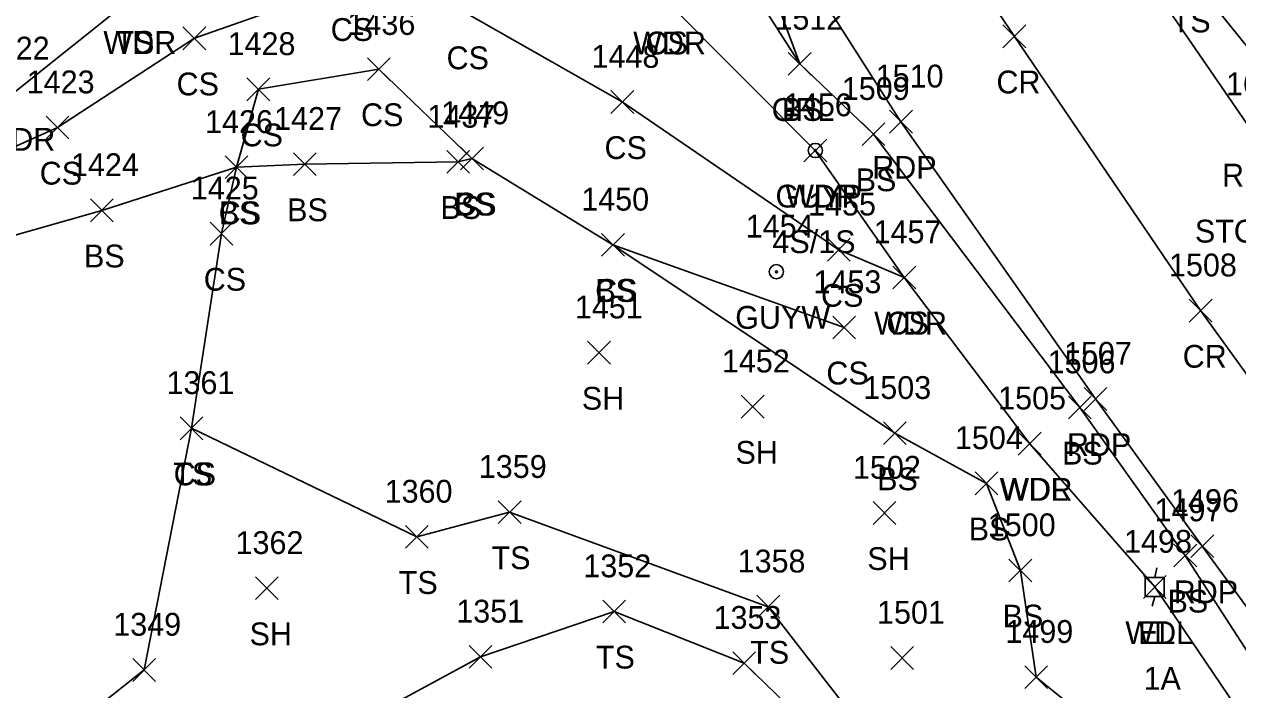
# Model space of a CAD drawing. Extents: x 1499292 to 1501024, y 534584 to 538043.
# Drawn here: x 1499781.4 to 1499887.8, y 537564.4 to 537622.8 of the extents above; entities that cross this region are included whole.
import ezdxf

# ---------------------------------------------------------------- set-up
doc = ezdxf.new("R2010")
doc.units = 0
for name, color, linetype in [('L_A', 7, 'Continuous'), ('L_I', 7, 'Continuous'), ('L_TIC', 7, 'Continuous'), ('LAWA', 7, 'Continuous'), ('LELB', 7, 'Continuous'), ('P_A', 7, 'Continuous'), ('P_I', 7, 'Continuous'), ('P_TIC', 7, 'Continuous'), ('PET', 7, 'Continuous'), ('PRC', 7, 'Continuous'), ('R_A', 7, 'Continuous'), ('R_I', 7, 'Continuous'), ('R_TIC', 7, 'Continuous'), ('RGR', 7, 'Continuous'), ('S_C', 7, 'Continuous'), ('U_A', 7, 'Continuous'), ('U_C', 7, 'Continuous'), ('U_I', 7, 'Continuous'), ('UEPT', 7, 'Continuous'), ('UPGW', 7, 'Continuous')]:
    doc.layers.add(name, color=color, linetype=linetype)

msp = doc.modelspace()

# ---------------------------------------------------------------- linework, layer by layer
at = {"layer": 'L_TIC'}
for points in [[(1499795.35, 537620.54), (1499797.35, 537622.54)], [(1499797.35, 537620.54), (1499795.35, 537622.54)], [(1499811.52, 537617.84), (1499813.52, 537619.84)], [(1499813.52, 537617.84), (1499811.52, 537619.84)], [(1499848.42, 537618.3), (1499850.42, 537620.3)], [(1499850.42, 537618.3), (1499848.42, 537620.3)], [(1499800.96, 537616.07), (1499802.96, 537618.07)], [(1499802.96, 537616.07), (1499800.96, 537618.07)], [(1499832.87, 537614.96), (1499834.87, 537616.96)], [(1499834.87, 537614.96), (1499832.87, 537616.96)], [(1499783.35, 537612.72), (1499785.35, 537614.72)], [(1499785.35, 537612.72), (1499783.35, 537614.72)], [(1499854.89, 537612.14), (1499856.89, 537614.14)], [(1499856.89, 537612.14), (1499854.89, 537614.14)], [(1499849.79, 537610.71), (1499851.79, 537612.71)], [(1499851.79, 537610.71), (1499849.79, 537612.71)], [(1499799.04, 537609.24), (1499801.04, 537611.24)], [(1499801.04, 537609.24), (1499799.04, 537611.24)], [(1499799.04, 537609.24), (1499801.04, 537611.24)], [(1499801.04, 537609.24), (1499799.04, 537611.24)], [(1499805.04, 537609.51), (1499807.04, 537611.51)], [(1499807.04, 537609.51), (1499805.04, 537611.51)], [(1499818.47, 537609.71), (1499820.47, 537611.71)], [(1499820.47, 537609.71), (1499818.47, 537611.71)], [(1499819.69, 537610.01), (1499821.69, 537612.01)], [(1499821.69, 537610.01), (1499819.69, 537612.01)], [(1499819.69, 537610.01), (1499821.69, 537612.01)], [(1499821.69, 537610.01), (1499819.69, 537612.01)], [(1499787.23, 537605.46), (1499789.23, 537607.46)], [(1499789.23, 537605.46), (1499787.23, 537607.46)], [(1499797.73, 537603.42), (1499799.73, 537605.42)], [(1499799.73, 537603.42), (1499797.73, 537605.42)], [(1499832.05, 537602.44), (1499834.05, 537604.44)], [(1499834.05, 537602.44), (1499832.05, 537604.44)], [(1499832.05, 537602.44), (1499834.05, 537604.44)], [(1499834.05, 537602.44), (1499832.05, 537604.44)], [(1499851.85, 537602.01), (1499853.85, 537604.01)], [(1499853.85, 537602.01), (1499851.85, 537604.01)], [(1499857.59, 537599.58), (1499859.59, 537601.58)], [(1499859.59, 537599.58), (1499857.59, 537601.58)], [(1499857.59, 537599.58), (1499859.59, 537601.58)], [(1499859.59, 537599.58), (1499857.59, 537601.58)], [(1499852.32, 537595.2), (1499854.32, 537597.2)], [(1499854.32, 537595.2), (1499852.32, 537597.2)], [(1499830.83, 537592.99), (1499832.83, 537594.99)], [(1499832.83, 537592.99), (1499830.83, 537594.99)], [(1499844.3, 537588.25), (1499846.3, 537590.25)], [(1499846.3, 537588.25), (1499844.3, 537590.25)], [(1499872.98, 537588.18), (1499874.98, 537590.18)], [(1499874.98, 537588.18), (1499872.98, 537590.18)], [(1499795.09, 537586.36), (1499797.09, 537588.36)], [(1499797.09, 537586.36), (1499795.09, 537588.36)], [(1499795.09, 537586.36), (1499797.09, 537588.36)], [(1499797.09, 537586.36), (1499795.09, 537588.36)], [(1499856.77, 537585.93), (1499858.77, 537587.93)], [(1499858.77, 537585.93), (1499856.77, 537587.93)], [(1499868.59, 537585.01), (1499870.59, 537587.01)], [(1499870.59, 537585.01), (1499868.59, 537587.01)], [(1499868.59, 537585.01), (1499870.59, 537587.01)], [(1499870.59, 537585.01), (1499868.59, 537587.01)], [(1499864.8, 537581.53), (1499866.8, 537583.53)], [(1499866.8, 537581.53), (1499864.8, 537583.53)], [(1499864.8, 537581.53), (1499866.8, 537583.53)], [(1499866.8, 537581.53), (1499864.8, 537583.53)], [(1499822.99, 537579.01), (1499824.99, 537581.01)], [(1499824.99, 537579.01), (1499822.99, 537581.01)], [(1499855.86, 537578.94), (1499857.86, 537580.94)], [(1499857.86, 537578.94), (1499855.86, 537580.94)], [(1499814.86, 537576.84), (1499816.86, 537578.84)], [(1499816.86, 537576.84), (1499814.86, 537578.84)], [(1499882.23, 537575.21), (1499884.23, 537577.21)], [(1499884.23, 537575.21), (1499882.23, 537577.21)], [(1499867.77, 537573.9), (1499869.77, 537575.9)], [(1499869.77, 537573.9), (1499867.77, 537575.9)], [(1499801.7, 537572.34), (1499803.7, 537574.34)], [(1499803.7, 537572.34), (1499801.7, 537574.34)], [(1499879.56, 537572.45), (1499881.56, 537574.45)], [(1499881.56, 537572.45), (1499879.56, 537574.45)], [(1499845.67, 537570.72), (1499847.67, 537572.72)], [(1499847.67, 537570.72), (1499845.67, 537572.72)], [(1499832.15, 537570.3), (1499834.15, 537572.3)], [(1499834.15, 537570.3), (1499832.15, 537572.3)], [(1499820.43, 537566.33), (1499822.43, 537568.33)], [(1499822.43, 537566.33), (1499820.43, 537568.33)], [(1499843.56, 537565.78), (1499845.56, 537567.78)], [(1499845.56, 537565.78), (1499843.56, 537567.78)], [(1499857.41, 537566.23), (1499859.41, 537568.23)], [(1499859.41, 537566.23), (1499857.41, 537568.23)], [(1499790.94, 537565.18), (1499792.94, 537567.18)], [(1499792.94, 537565.18), (1499790.94, 537567.18)], [(1499869.16, 537564.55), (1499871.16, 537566.55)], [(1499871.16, 537564.55), (1499869.16, 537566.55)]]:
    msp.add_lwpolyline(points, dxfattribs=at)
at = {"layer": 'LAWA'}
for points in [[(1499698.66, 537594.11), (1499723.53, 537594.31), (1499742.5, 537597.2), (1499755.39, 537600.74), (1499766.05, 537611.81), (1499780.4, 537616.68), (1499791.01, 537625.18), (1499801.2, 537633.98), (1499806.37, 537638.04), (1499812.35, 537644.38), (1499819.03, 537655.55), (1499823.79, 537650.94), (1499829.05, 537643.26), (1499835.12, 537630.39), (1499837.46, 537625.13), (1499850.79, 537611.71), (1499858.59, 537600.58), (1499869.59, 537586.01)], [(1499995.76, 537480.13), (1499987.71, 537481.12), (1499965.63, 537488.45), (1499951.19, 537496.8), (1499940.31, 537506.49), (1499921.73, 537516.37), (1499909.85, 537530.28), (1499895.31, 537551.67), (1499880.56, 537573.45), (1499869.59, 537586.01)]]:
    msp.add_lwpolyline(points, dxfattribs=at)
at = {"layer": 'LELB'}
for points in [[(1499982.95, 537489.68), (1499966.99, 537494.97), (1499951.63, 537501.69), (1499942.17, 537508.92), (1499936.88, 537512.97), (1499930.43, 537522.3), (1499913.7, 537537.04), (1499897.54, 537554.09), (1499883.23, 537576.21), (1499873.98, 537589.18), (1499855.89, 537613.14), (1499849.42, 537619.3), (1499842.66, 537629.92), (1499836.97, 537639.79), (1499825.94, 537654.56), (1499819.31, 537659.47)], [(1499875.63, 537635.39), (1499883.62, 537627.06), (1499893.29, 537615.08), (1499899.95, 537610.95), (1499909.18, 537610.06), (1499915.74, 537611.14), (1499937.58, 537622.68), (1499960.48, 537631.23), (1499993.02, 537642.59), (1500017.77, 537650.35)], [(1499756.09, 537597.24), (1499767.63, 537606.22), (1499784.35, 537613.72), (1499796.35, 537621.54), (1499809.86, 537626.31), (1499820.02, 537623.83), (1499833.87, 537615.96), (1499852.85, 537603.01), (1499858.59, 537600.58)], [(1499779.18, 537556.08), (1499791.94, 537566.18), (1499796.09, 537587.36), (1499798.73, 537604.42), (1499800.04, 537610.24), (1499801.96, 537617.07), (1499812.52, 537618.84), (1499820.69, 537611.01), (1499833.05, 537603.44), (1499853.32, 537596.2)], [(1499779.42, 537543.38), (1499779.18, 537556.08), (1499776.35, 537572.85), (1499776.42, 537583.06), (1499772.5, 537594.14), (1499773.52, 537602.27), (1499788.23, 537606.46), (1499800.04, 537610.24), (1499806.04, 537610.51), (1499819.47, 537610.71), (1499820.69, 537611.01), (1499833.05, 537603.44), (1499857.77, 537586.93), (1499865.8, 537582.53)], [(1499921.73, 537516.37), (1499905.45, 537524.8), (1499883.33, 537538.36), (1499865, 537549.13), (1499857.17, 537558.16), (1499846.67, 537571.72), (1499823.99, 537580.01), (1499815.86, 537577.84), (1499796.09, 537587.36)], [(1499926.59, 537517.73), (1499909.85, 537530.28), (1499890.98, 537548.56), (1499870.16, 537565.55), (1499868.77, 537574.9), (1499865.8, 537582.53)], [(1499800.93, 537550.38), (1499802.71, 537554.8), (1499804.45, 537558.13), (1499821.43, 537567.33), (1499833.15, 537571.3), (1499844.56, 537566.78), (1499853.87, 537557.75), (1499860.98, 537548.39)]]:
    msp.add_lwpolyline(points, dxfattribs=at)
at = {"layer": 'P_TIC'}
for points in [[(1499867.24, 537620.71), (1499869.24, 537622.71)], [(1499869.24, 537620.71), (1499867.24, 537622.71)], [(1499857.3, 537613.23), (1499859.3, 537615.23)], [(1499859.3, 537613.23), (1499857.3, 537615.23)], [(1499883.57, 537596.67), (1499885.57, 537598.67)], [(1499885.57, 537596.67), (1499883.57, 537598.67)], [(1499874.36, 537588.93), (1499876.36, 537590.93)], [(1499876.36, 537588.93), (1499874.36, 537590.93)], [(1499883.72, 537576.02), (1499885.72, 537578.02)], [(1499885.72, 537576.02), (1499883.72, 537578.02)]]:
    msp.add_lwpolyline(points, dxfattribs=at)
at = {"layer": 'PET'}
msp.add_lwpolyline([(1499898.17, 537558.63), (1499884.72, 537577.02), (1499875.36, 537589.93), (1499858.3, 537614.23), (1499840.48, 537642.14), (1499830.34, 537658.34), (1499824.74, 537665.44), (1499832.02, 537672.42), (1499839.24, 537678.69), (1499843.34, 537674.16), (1499846.69, 537670.95), (1499854.16, 537663.15), (1499866.61, 537649.91), (1499874.55, 537641.32), (1499875.63, 537635.39), (1499877.01, 537630.96), (1499888.96, 537613.55)], dxfattribs=at)
at = {"layer": 'PRC'}
msp.add_lwpolyline([(1500278.96, 537330.13), (1500245.16, 537363.32), (1500217.07, 537386.35), (1500194.78, 537402.07), (1500161.59, 537424.07), (1500124.89, 537444.32), (1500077.4, 537466.83), (1500048.03, 537479.39), (1500024.1, 537489.28), (1500002.86, 537498.23), (1499984.27, 537507.12), (1499965.54, 537516.89), (1499943.1, 537532.26), (1499924.7, 537548.4), (1499906.7, 537567.9), (1499892.97, 537586.05), (1499884.57, 537597.67), (1499868.24, 537621.71), (1499849.2, 537650.1), (1499837.66, 537665.34), (1499832.02, 537672.42)], dxfattribs=at)
at = {"layer": 'R_TIC'}
for points in [[(1499848.42, 537618.3), (1499850.42, 537620.3)], [(1499850.42, 537618.3), (1499848.42, 537620.3)]]:
    msp.add_lwpolyline(points, dxfattribs=at)
at = {"layer": 'RGR'}
msp.add_lwpolyline([(1499849.42, 537619.3), (1499844.98, 537631.26), (1499840.01, 537641.78), (1499824.37, 537665.24)], dxfattribs=at)
at = {"layer": 'UEPT'}
for p, q in [((1499880.72, 537575.12), (1499880.56, 537574.28)), ((1499879.72, 537572.62), (1499879.72, 537574.28)), ((1499879.72, 537574.28), (1499881.39, 537574.28)), ((1499881.39, 537574.28), (1499881.39, 537572.62)), ((1499880.56, 537573.45), (1499880.56, 537573.45)), ((1499881.39, 537572.62), (1499879.72, 537572.62)), ((1499880.31, 537571.78), (1499880.56, 537572.62))]:
    msp.add_line(p, q, dxfattribs=at)
at = {"layer": 'UPGW'}
for centre, radius in [((1499850.79, 537611.71), 0.625), ((1499850.79, 537611.71), 0.0833), ((1499847.38, 537601.08), 0.625), ((1499847.38, 537601.08), 0.0833)]:
    msp.add_circle(centre, radius, dxfattribs=at)

# ---------------------------------------------------------------- texts
at = {"layer": 'L_A'}
for s, p in [('TS', (1499882.03, 537622.06)), ('CS', (1499808.3, 537621.31)), ('WDR', (1499788.37, 537620.18)), ('TS', (1499789.42, 537620.18)), ('WDR', (1499834.82, 537620.13)), ('CS', (1499835.9, 537620.13)), ('CS', (1499818.46, 537618.83)), ('CS', (1499794.79, 537616.54)), ('BS', (1499847.86, 537614.3)), ('CS', (1499810.96, 537613.84)), ('WDR', (1499777.77, 537611.68)), ('CS', (1499800.4, 537612.07)), ('CS', (1499832.31, 537610.96)), ('CS', (1499782.79, 537608.72)), ('BS', (1499854.33, 537608.14)), ('CS', (1499819.13, 537606.01)), ('BS', (1499819.13, 537606.01)), ('WDR', (1499848.15, 537606.71)), ('CS', (1499798.48, 537605.24)), ('BS', (1499798.48, 537605.24)), ('BS', (1499804.48, 537605.51)), ('BS', (1499817.92, 537605.71)), ('BS', (1499786.67, 537601.46)), ('CS', (1499797.17, 537599.42)), ('CS', (1499831.49, 537598.44)), ('BS', (1499831.49, 537598.44)), ('CS', (1499851.29, 537598.01)), ('WDR', (1499855.95, 537595.58)), ('CS', (1499857.03, 537595.58)), ('CS', (1499851.76, 537591.2)), ('SH', (1499830.32, 537588.99)), ('SH', (1499843.79, 537584.25)), ('BS', (1499872.42, 537584.18)), ('TS', (1499794.5, 537582.36)), ('CS', (1499794.53, 537582.36)), ('BS', (1499856.21, 537581.93)), ('WDR', (1499866.95, 537581.01)), ('WDL', (1499867.01, 537581.01)), ('BS', (1499864.24, 537577.53)), ('BS', (1499864.24, 537577.53)), ('TS', (1499822.4, 537575.01)), ('SH', (1499855.35, 537574.94)), ('TS', (1499814.27, 537572.84)), ('BS', (1499881.67, 537571.21)), ('BS', (1499867.21, 537569.9)), ('SH', (1499801.19, 537568.34)), ('WDL', (1499877.97, 537568.45)), ('TS', (1499845.08, 537566.72)), ('TS', (1499831.55, 537566.3))]:
    msp.add_text(s, height=2, dxfattribs=at).set_placement(p)
at = {"layer": 'L_I'}
for s, p in [('1436', (1499809.77, 537621.84)), ('1512', (1499847.29, 537622.3)), ('1422', (1499777.71, 537619.68)), ('1428', (1499799.26, 537620.07)), ('1448', (1499831.17, 537618.96)), ('1423', (1499781.65, 537616.72)), ('1509', (1499853.11, 537616.14)), ('1456', (1499848.04, 537614.71)), ('1426', (1499797.29, 537613.24)), ('1426', (1499797.29, 537613.24)), ('1427', (1499803.34, 537613.51)), ('1437', (1499816.78, 537613.71)), ('1449', (1499817.99, 537614.01)), ('1449', (1499817.99, 537614.01)), ('1424', (1499785.53, 537609.46)), ('1425', (1499796.04, 537607.42)), ('1450', (1499830.27, 537606.44)), ('1450', (1499830.27, 537606.44)), ('1455', (1499850.16, 537606.01)), ('1457', (1499855.9, 537603.58)), ('1457', (1499855.9, 537603.58)), ('1453', (1499850.63, 537599.2)), ('1451', (1499829.71, 537596.99)), ('1452', (1499842.6, 537592.25)), ('1506', (1499871.16, 537592.18)), ('1361', (1499793.91, 537590.36)), ('1361', (1499793.91, 537590.36)), ('1503', (1499855, 537589.93)), ('1505', (1499866.82, 537589.01)), ('1505', (1499866.82, 537589.01)), ('1504', (1499863.03, 537585.53)), ('1504', (1499863.03, 537585.53)), ('1359', (1499821.29, 537583.01)), ('1502', (1499854.09, 537582.94)), ('1360', (1499813.03, 537580.84)), ('1497', (1499880.53, 537579.21)), ('1500', (1499865.91, 537577.9)), ('1362', (1499799.96, 537576.34)), ('1498', (1499877.86, 537576.45)), ('1352', (1499830.45, 537574.3)), ('1358', (1499843.98, 537574.72)), ('1351', (1499819.31, 537570.33)), ('1353', (1499841.87, 537569.78)), ('1501', (1499856.2, 537570.23)), ('1349', (1499789.24, 537569.18)), ('1499', (1499867.46, 537568.55))]:
    msp.add_text(s, height=2, dxfattribs=at).set_placement(p)
at = {"layer": 'P_A'}
for s, p in [('CR', (1499866.67, 537616.71)), ('RDP', (1499855.78, 537609.23)), ('RDP', (1499886.45, 537608.55)), ('RDP', (1499886.45, 537608.55)), ('CR', (1499883, 537592.67)), ('RDP', (1499872.85, 537584.93)), ('RDP', (1499882.21, 537572.02))]:
    msp.add_text(s, height=2, dxfattribs=at).set_placement(p)
at = {"layer": 'P_I'}
for s, p in [('1510', (1499856.08, 537617.23)), ('1612', (1499886.79, 537616.55)), ('1612', (1499886.79, 537616.55)), ('1508', (1499881.8, 537600.67)), ('1507', (1499872.59, 537592.93)), ('1496', (1499881.98, 537580.02))]:
    msp.add_text(s, height=2, dxfattribs=at).set_placement(p)
at = {"layer": 'R_A'}
msp.add_text('GRL', height=2, dxfattribs=at).set_placement((1499846.96, 537614.3))
at = {"layer": 'R_I'}
msp.add_text('1512', height=2, dxfattribs=at).set_placement((1499847.29, 537622.3))
at = {"layer": 'S_C'}
msp.add_text('STOP NATUREL TRNPK', height=2, dxfattribs=at).set_placement((1499884.07, 537603.64))
at = {"layer": 'U_A'}
for s, p in [('GUYP', (1499847.3, 537606.71)), ('GUYW', (1499843.77, 537596.08)), ('EL', (1499879.09, 537568.45))]:
    msp.add_text(s, height=2, dxfattribs=at).set_placement(p)
at = {"layer": 'U_C'}
for s, p in [('4S/1S', (1499847.03, 537602.71)), ('1A', (1499879.57, 537564.45))]:
    msp.add_text(s, height=2, dxfattribs=at).set_placement(p)
at = {"layer": 'U_I'}
for s, p in [('1456', (1499848.04, 537614.71)), ('1454', (1499844.69, 537604.08)), ('1498', (1499877.86, 537576.45))]:
    msp.add_text(s, height=2, dxfattribs=at).set_placement(p)

doc.saveas('drawing.dxf')
